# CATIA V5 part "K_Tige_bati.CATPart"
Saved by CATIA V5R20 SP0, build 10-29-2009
Part number: tige_bati
Publications: "longeur_tige_1", "rayon_tige_1"
Bounding box of the stored display mesh (mm): x -5 to 5, y -70 to 70, z -4.991 to 4.991
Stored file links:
  G:\Khaled_CFAO_2011\SIL\SIL_GR1\mroland\Khaled\CAD_CATIA_Modifie\K_Tige_bati.CATPart
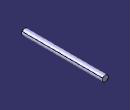
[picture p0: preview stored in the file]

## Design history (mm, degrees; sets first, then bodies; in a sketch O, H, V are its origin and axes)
Parameters
  longeur_tige_1 = 140 mm
  rayon_tige_1 = 5 mm
Set1
  Sketch1 on xy-plane, origin (0, 0, 0), H (1, 0, 0), V (0, 1, 0)
    line L1 (0, 70) -> (5, 70)
    line L2 (5, 70) -> (5, -70)
    line L3 (5, -70) -> (0, -70)
    line L4 (0, -70) -> (0, 70)
    length L4 = 140 {= longeur_tige_1}
    length L1 = 5 {= rayon_tige_1}
    horizontal: L1 H, L3 H
    vertical: L2 V, L4 V
Body1 (main body)
  Shaft1: profile Sketch1, axis Sketch1.L4, angle 360
  Sketch2 on zx-plane, origin (0, 0, 0), H (-1, 0, 0), V (0, 0, 1)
